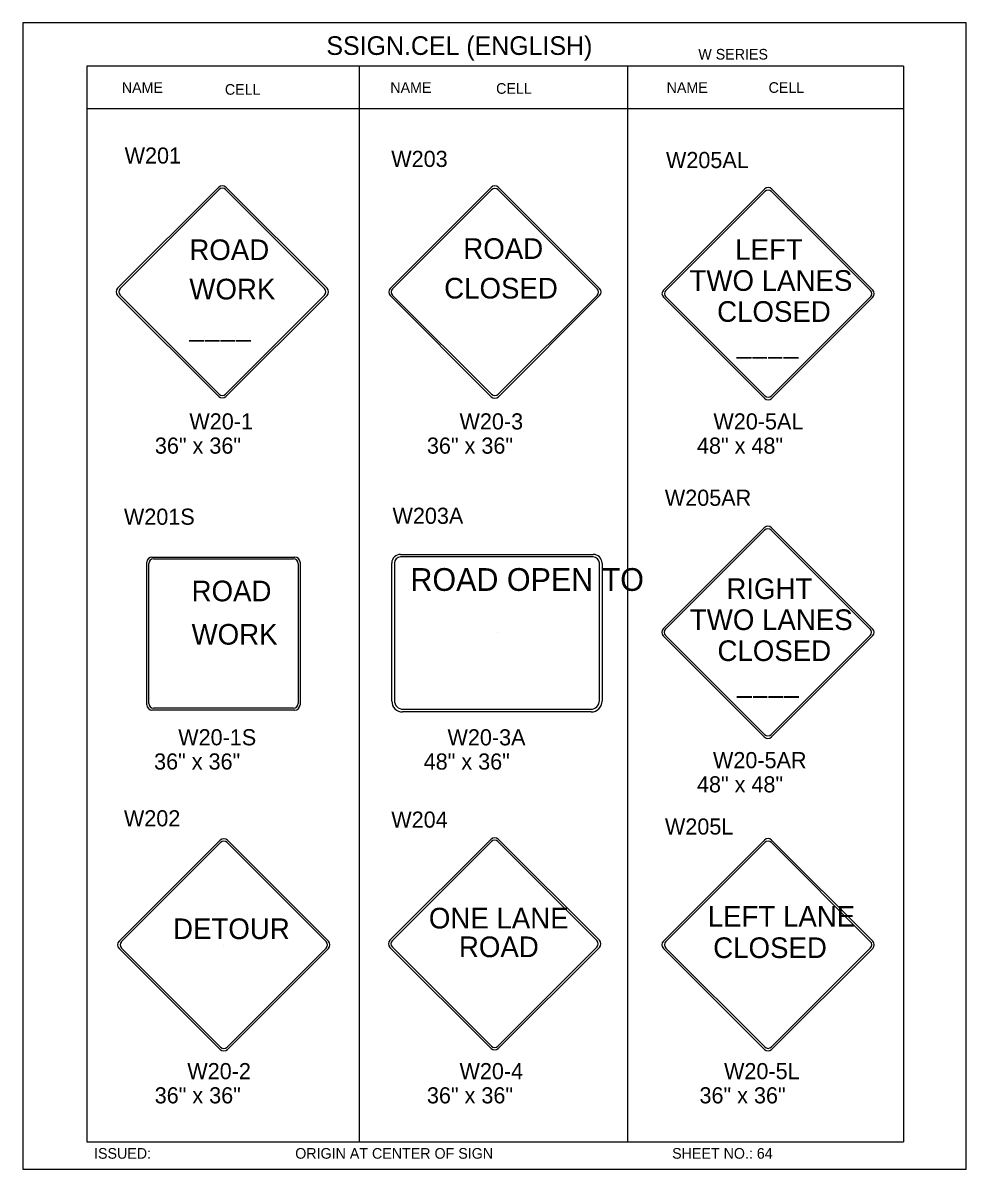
# Model space of a CAD drawing. Extents: x -5299 to 22597, y -19549 to -1808.
# Drawn here: x 2593 to 3294, y -7309 to -6456 of the extents above; entities that cross this region are included whole.
import ezdxf

# ---------------------------------------------------------------- set-up
doc = ezdxf.new("R2010")
doc.units = 0
for name, color, linetype in [('Level 1', 7, 'Continuous'), ('Level 2', 7, 'Continuous'), ('Level 3', 7, 'Continuous'), ('Level 62', 7, 'Continuous')]:
    doc.layers.add(name, color=color, linetype=linetype)

msp = doc.modelspace()

# ---------------------------------------------------------------- linework, layer by layer
at = {"layer": 'Level 1'}
for p, q in [((3247.67, -6488.59), (2640.66, -6488.59)), ((2640.66, -6488.59), (2640.66, -7288.59)), ((2842.99, -6488.59), (2842.99, -7288.59)), ((3042.45, -6488.59), (3042.45, -7288.59)), ((3247.67, -6488.59), (3247.67, -7288.59)), ((3247.67, -6520.26), (2640.66, -6520.26)), ((2663.54, -6653.73), (2738.68, -6578.59)), ((2744.04, -6578.59), (2819.18, -6653.73)), ((2866.16, -6653.86), (2941.29, -6578.73)), ((2946.66, -6578.73), (3021.8, -6653.86)), ((3069.25, -6655.08), (3144.38, -6579.96)), ((3149.74, -6579.96), (3224.87, -6655.08)), ((2665.33, -6653.95), (2738.9, -6580.38)), ((2743.82, -6580.38), (2817.39, -6653.95)), ((2867.95, -6654.08), (2941.52, -6580.52)), ((2946.44, -6580.52), (3020.01, -6654.08)), ((3071.04, -6655.31), (3144.6, -6581.75)), ((3149.52, -6581.75), (3223.08, -6655.31)), ((2741.36, -6656.41), (2741.36, -6656.41)), ((2943.98, -6656.54), (2943.98, -6656.54)), ((2738.68, -6734.23), (2663.54, -6659.1)), ((2738.9, -6732.44), (2665.33, -6658.87)), ((2817.39, -6658.87), (2743.82, -6732.44)), ((2819.18, -6659.1), (2744.04, -6734.23)), ((2941.3, -6734.36), (2866.16, -6659.23)), ((2941.52, -6732.57), (2867.95, -6659)), ((3020.01, -6659), (2946.44, -6732.57)), ((3021.8, -6659.23), (2946.66, -6734.36)), ((3144.38, -6735.57), (3069.26, -6660.45)), ((3144.6, -6733.78), (3071.04, -6660.23)), ((3147.07, -6657.77), (3147.07, -6657.77)), ((3223.08, -6660.23), (3149.52, -6733.78)), ((3224.87, -6660.45), (3149.74, -6735.57)), ((3069.11, -6906.91), (3144.23, -6831.79)), ((3070.89, -6907.14), (3144.45, -6833.58)), ((3149.37, -6833.58), (3222.93, -6907.14)), ((3149.6, -6831.79), (3224.72, -6906.91)), ((2873.85, -6851.61), (3017.07, -6851.61)), ((2685.29, -6963.64), (2685.29, -6857.39)), ((2686.71, -6962.54), (2686.71, -6858.49)), ((2689.08, -6853.59), (2795.34, -6853.59)), ((2690.19, -6855.02), (2794.23, -6855.02)), ((2797.71, -6858.49), (2797.71, -6962.54)), ((2799.14, -6857.39), (2799.14, -6963.64)), ((2867.34, -6960.79), (2867.34, -6858.12)), ((3023.58, -6858.12), (3023.58, -6960.79)), ((2742.21, -6910.52), (2742.21, -6910.52)), ((2945.6, -6909.68), (2945.6, -6909.68)), ((3144.23, -6987.4), (3069.11, -6912.28)), ((3144.45, -6985.61), (3070.89, -6912.05)), ((3147.44, -6909.31), (3147.44, -6909.31)), ((3222.93, -6912.05), (3149.37, -6985.61)), ((3224.72, -6912.28), (3149.59, -6987.4)), ((2795.34, -6967.44), (2689.08, -6967.44)), ((2794.23, -6966.02), (2690.19, -6966.02)), ((3015.58, -6968.79), (2875.34, -6968.79)), ((2664.63, -7139.32), (2739.76, -7064.19)), ((2666.42, -7139.55), (2739.99, -7065.98)), ((2744.91, -7065.98), (2818.47, -7139.55)), ((2745.13, -7064.19), (2820.26, -7139.32)), ((2865.96, -7138.59), (2941.1, -7063.45)), ((2867.75, -7138.81), (2941.32, -7065.24)), ((2946.24, -7065.24), (3019.81, -7138.81)), ((2946.46, -7063.45), (3021.6, -7138.59)), ((3069.18, -7139.26), (3144.32, -7064.12)), ((3070.97, -7139.48), (3144.54, -7065.91)), ((3149.46, -7065.91), (3223.03, -7139.48)), ((3149.68, -7064.12), (3224.82, -7139.26)), ((2742.5, -7142.18), (2742.5, -7142.18)), ((2943.78, -7140.97), (2943.78, -7140.97)), ((3147.77, -7142.18), (3147.77, -7142.18)), ((2739.76, -7219.83), (2664.63, -7144.69)), ((2739.99, -7218.04), (2666.41, -7144.47)), ((2818.47, -7144.47), (2744.91, -7218.04)), ((2820.26, -7144.69), (2745.13, -7219.83)), ((2941.1, -7219.09), (2865.96, -7143.95)), ((2941.32, -7217.3), (2867.75, -7143.73)), ((3019.81, -7143.73), (2946.24, -7217.3)), ((3021.6, -7143.95), (2946.46, -7219.09)), ((3144.32, -7219.76), (3069.18, -7144.62)), ((3144.54, -7217.97), (3070.97, -7144.4)), ((3223.03, -7144.4), (3149.46, -7217.97)), ((3224.82, -7144.62), (3149.68, -7219.76)), ((2640.66, -7288.59), (3247.67, -7288.59))]:
    msp.add_line(p, q, dxfattribs=at)
for centre, radius, start, end in [((2741.36, -6581.28), 3.79, 45, 135), ((2741.36, -6582.84), 3.48, 45, 135), ((2943.98, -6581.41), 3.79, 45, 135), ((2943.98, -6582.97), 3.48, 45, 135), ((3147.06, -6582.64), 3.79, 45, 135), ((3147.06, -6584.21), 3.48, 45, 135), ((2666.22, -6656.41), 3.79, 135, 225), ((2667.79, -6656.41), 3.48, 135, 225), ((2814.93, -6656.41), 3.48, 315, 45), ((2816.49, -6656.41), 3.79, 315, 45), ((2868.84, -6656.54), 3.79, 135, 225), ((2870.41, -6656.54), 3.48, 135, 225), ((3017.55, -6656.54), 3.48, 315, 45), ((3019.11, -6656.54), 3.79, 315, 45), ((3071.94, -6657.77), 3.79, 135, 225), ((3073.5, -6657.77), 3.48, 135, 225), ((3220.62, -6657.77), 3.48, 315, 45), ((3222.18, -6657.77), 3.79, 315, 45), ((2741.36, -6729.98), 3.48, 225, 315), ((2943.98, -6730.11), 3.48, 225, 315), ((3147.06, -6731.32), 3.48, 225, 315), ((2741.36, -6731.55), 3.79, 225, 315), ((2943.98, -6731.68), 3.79, 225, 315), ((3147.06, -6732.89), 3.79, 225, 315), ((3146.91, -6834.47), 3.79, 45, 135), ((3146.91, -6836.04), 3.48, 45, 135), ((2873.85, -6858.12), 6.51, 90, 180), ((3017.07, -6858.12), 6.51, 0, 90), ((2689.08, -6857.39), 3.79, 90, 180), ((2690.19, -6858.49), 3.48, 90, 180), ((2794.23, -6858.49), 3.48, 0, 90), ((2795.34, -6857.39), 3.79, 0, 90), ((3071.79, -6909.59), 3.79, 135, 225), ((3073.35, -6909.59), 3.48, 135, 225), ((3220.47, -6909.59), 3.48, 315, 45), ((3222.03, -6909.59), 3.79, 315, 45), ((2689.08, -6963.64), 3.79, 180, 270), ((2690.19, -6962.54), 3.48, 180, 270), ((2794.23, -6962.54), 3.48, 270, 0), ((2795.34, -6963.64), 3.79, 270, 0), ((2875.34, -6960.79), 8, 180, 270), ((3015.58, -6960.79), 8, 270, 0), ((3146.91, -6984.72), 3.79, 225, 315), ((3146.91, -6983.15), 3.48, 225, 315), ((2742.44, -7066.87), 3.79, 45, 135), ((2742.44, -7068.44), 3.48, 45, 135), ((2943.78, -7066.13), 3.8, 45, 135), ((2943.78, -7067.7), 3.48, 45, 135), ((3147, -7066.8), 3.8, 45, 135), ((3147, -7068.37), 3.48, 45, 135), ((2667.31, -7142.01), 3.79, 135, 225), ((2668.88, -7142.01), 3.48, 135, 225), ((2816.01, -7142.01), 3.48, 315, 45), ((2817.58, -7142.01), 3.79, 315, 45), ((2868.64, -7141.27), 3.8, 135, 225), ((2870.21, -7141.27), 3.48, 135, 225), ((3017.35, -7141.27), 3.48, 315, 45), ((3018.92, -7141.27), 3.8, 315, 45), ((3071.86, -7141.94), 3.8, 135, 225), ((3073.43, -7141.94), 3.48, 135, 225), ((3220.57, -7141.94), 3.48, 315, 45), ((3222.14, -7141.94), 3.8, 315, 45), ((2742.44, -7215.58), 3.48, 225, 315), ((2943.78, -7216.41), 3.8, 225, 315), ((2943.78, -7214.84), 3.48, 225, 315), ((3147, -7215.51), 3.48, 225, 315), ((2742.44, -7217.14), 3.79, 225, 315), ((3147, -7217.08), 3.8, 225, 315)]:
    msp.add_arc(centre, radius, start, end, dxfattribs=at)
at = {"layer": 'Level 3'}
for p, q in [((2869.3, -6858.12), (2869.3, -6960.33)), ((3017.07, -6853.57), (2873.85, -6853.57)), ((3021.63, -6960.33), (3021.63, -6858.12)), ((2875.8, -6966.84), (3015.12, -6966.84))]:
    msp.add_line(p, q, dxfattribs=at)
for centre, radius, start, end in [((2873.85, -6858.12), 4.56, 90, 180), ((3017.07, -6858.12), 4.56, 0, 90), ((2875.81, -6960.33), 6.51, 180, 270), ((3015.12, -6960.33), 6.51, 270, 0)]:
    msp.add_arc(centre, radius, start, end, dxfattribs=at)
at = {"layer": 'Level 62'}
msp.add_lwpolyline([(2593.15, -7308.78), (3294.2, -7308.78), (3294.2, -6456.4), (2593.15, -6456.4)], close=True, dxfattribs=at)

# ---------------------------------------------------------------- texts
at = {"layer": 'Level 1'}
for s, height, p in [('ROAD', 15.368, (2716.85, -6632.8)), ('ROAD', 15.368, (2920.48, -6631.91)), ('LEFT', 15.368, (3122.58, -6632.59)), ('WORK', 15.368, (2716.85, -6662.03)), ('CLOSED', 15.368, (2906.26, -6661.37)), ('TWO LANES', 15.368, (3088.62, -6655.65)), ('CLOSED', 15.368, (3109.14, -6678.7)), ('____', 15.367, (2716.85, -6689.09)), ('____', 15.368, (3123.77, -6701.76)), ('RIGHT', 15.368, (3116, -6884.84)), ('ROAD', 15.368, (2718.51, -6886.53)), ('TWO LANES', 15.368, (3088.89, -6907.9)), ('WORK', 15.368, (2718.51, -6918.77)), ('CLOSED', 15.368, (3109.41, -6930.96)), ('____', 15.368, (3124.05, -6954.02)), ('ONE LANE', 15.368, (2894.88, -7129.84)), ('LEFT LANE', 15.368, (3102.16, -7128.48)), ('DETOUR', 15.368, (2704.73, -7137.76)), ('ROAD', 15.368, (2917.24, -7151.18)), ('CLOSED', 15.368, (3106.23, -7151.85))]:
    msp.add_text(s, height=height, dxfattribs=at).set_placement(p)
at = {"layer": 'Level 2'}
for s, p in [('W201', (2668.75, -6561.01)), ('W203', (2866.93, -6563.52)), ('W205AL', (3071.13, -6564.36)), ('W205AR', (3070.29, -6815.52)), ('W201S', (2668.22, -6829.62)), ('W203A', (2867.87, -6828.92)), ('W202', (2668.21, -7053.9)), ('W204', (2866.95, -7054.89)), ('W205L', (3070.37, -7060.01))]:
    msp.add_text(s, height=12, dxfattribs=at).set_placement(p)
at = {"layer": 'Level 3'}
for s, height, p in [('SSIGN.CEL (ENGLISH)', 13.8566, (2818.73, -6480.2)), ('W SERIES', 7.918, (3095.17, -6483.64)), ('NAME', 7.918, (2666.66, -6508.42)), ('CELL', 7.918, (2743.27, -6509.82)), ('NAME', 7.918, (2866.23, -6508.42)), ('CELL', 7.918, (2944.88, -6509.12)), ('NAME', 7.918, (3071.62, -6508.42)), ('CELL', 7.918, (3147.42, -6508.42)), ('W20-1', 12, (2716.85, -6758.75)), ('W20-3', 12, (2917.68, -6758.75)), ('W20-5AL', 12, (3106.4, -6758.75)), ('36" x 36"', 12, (2691.24, -6776.75)), ('36" x 36"', 12, (2893.44, -6776.75)), ('48" x 48"', 12, (3094.17, -6776.75)), ('ROAD OPEN TO ', 16.9255, (2881.2, -6878.79)), ('W20-1S', 12, (2708.58, -6993.65)), ('W20-3A', 12, (2908.75, -6993.69)), ('36" x 36"', 12, (2690.63, -7011.65)), ('48" x 36"', 12, (2891.03, -7011.69)), ('W20-5AR', 12, (3106.07, -7010.65)), ('48" x 48"', 12, (3094.17, -7028.65)), ('W20-2', 12, (2715.33, -7241.93)), ('W20-4', 12, (2917.68, -7241.93)), ('W20-5L', 12, (3114.28, -7241.93)), ('36" x 36"', 12, (2691.09, -7259.93)), ('36" x 36"', 12, (2893.44, -7259.93)), ('36" x 36"', 12, (3096.04, -7259.93)), ('ISSUED:', 7.918, (2646.02, -7301.08)), ('ORIGIN AT CENTER OF SIGN', 7.9181, (2795.55, -7301.08)), ('SHEET NO.: 64', 7.918, (3075.71, -7301.08))]:
    msp.add_text(s, height=height, dxfattribs=at).set_placement(p)

doc.saveas('drawing.dxf')
